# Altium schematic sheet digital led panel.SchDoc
size A4; SheetNumber: 1; SheetTotal: 2; SPICEModelCacheRHZGLBES: <root> / <DocumentId>RHZGLBES</DocumentId> / </root>
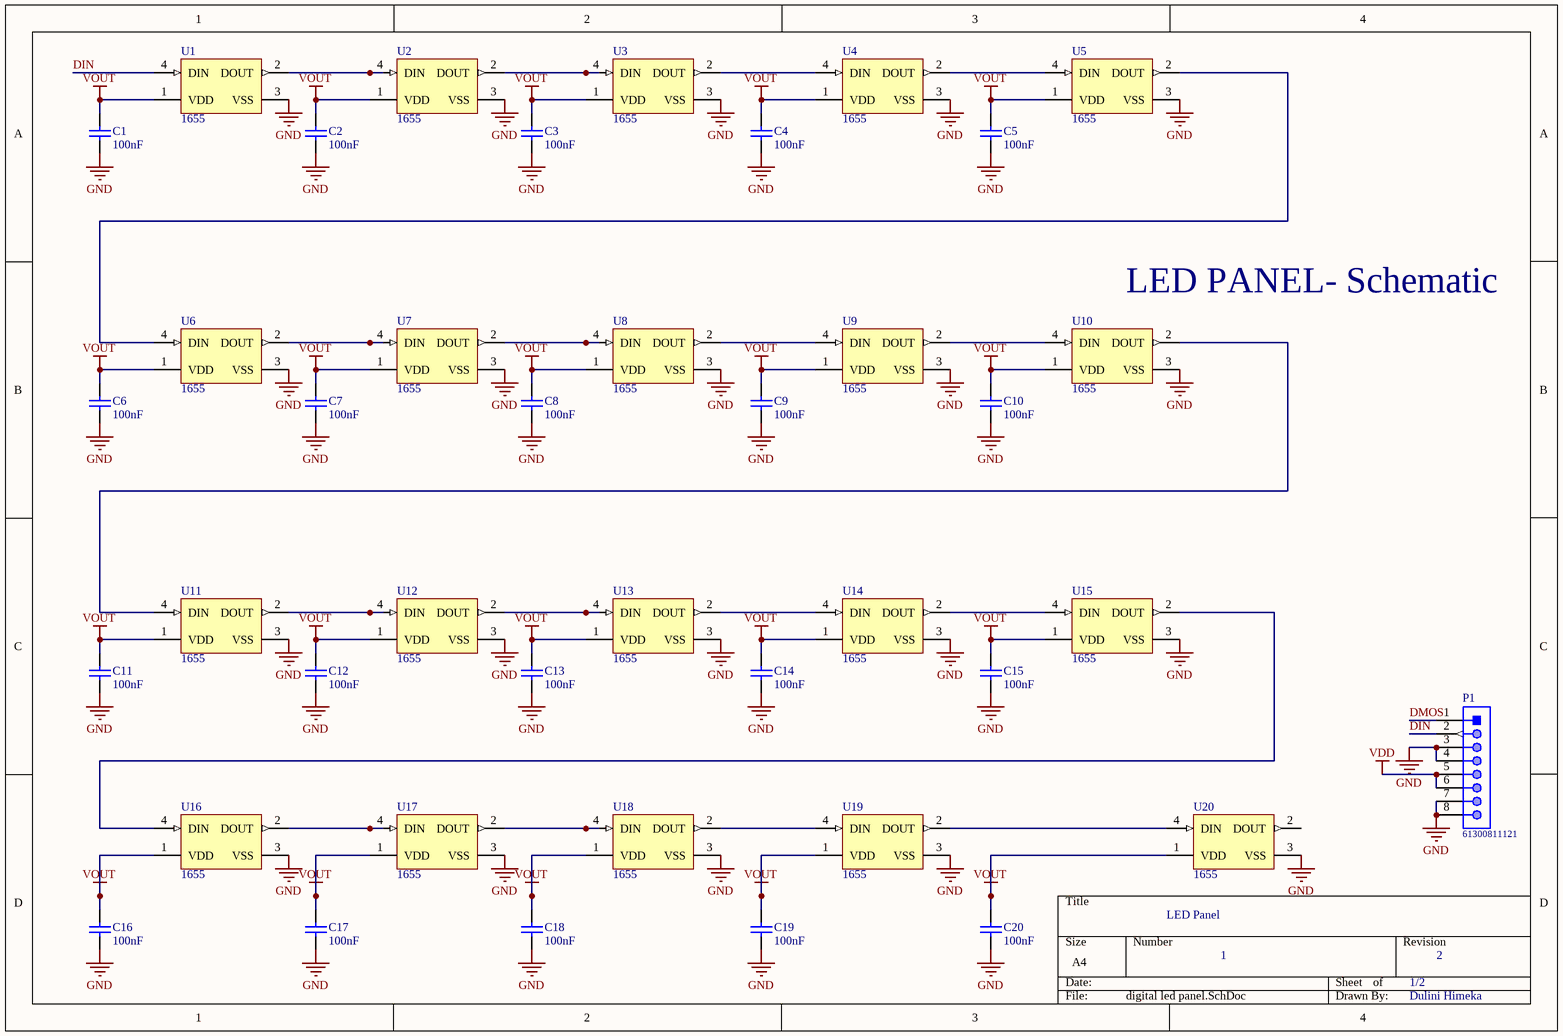
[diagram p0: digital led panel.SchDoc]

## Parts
C1  100nF  [KEMT-1206-2_M]
C2  100nF  [KEMT-1206-2_M]
C3  100nF  [KEMT-1206-2_M]
C4  100nF  [KEMT-1206-2_M]
C5  100nF  [KEMT-1206-2_M]
C6  100nF  [KEMT-1206-2_M]
C7  100nF  [KEMT-1206-2_M]
C8  100nF  [KEMT-1206-2_M]
C9  100nF  [KEMT-1206-2_M]
C10  100nF  [KEMT-1206-2_M]
C11  100nF  [KEMT-1206-2_M]
C12  100nF  [KEMT-1206-2_M]
C13  100nF  [KEMT-1206-2_M]
C14  100nF  [KEMT-1206-2_M]
C15  100nF  [KEMT-1206-2_M]
C16  100nF  [KEMT-1206-2_M]
C17  100nF  [KEMT-1206-2_M]
C18  100nF  [KEMT-1206-2_M]
C19  100nF  [KEMT-1206-2_M]
C20  100nF  [KEMT-1206-2_M]
P1  61300811121  [61300811121]
U1  1655  [ADA-RGB-1655_V]
U2  1655  [ADA-RGB-1655_V]
U3  1655  [ADA-RGB-1655_V]
U4  1655  [ADA-RGB-1655_V]
U5  1655  [ADA-RGB-1655_V]
U6  1655  [ADA-RGB-1655_V]
U7  1655  [ADA-RGB-1655_V]
U8  1655  [ADA-RGB-1655_V]
U9  1655  [ADA-RGB-1655_V]
U10  1655  [ADA-RGB-1655_V]
U11  1655  [ADA-RGB-1655_V]
U12  1655  [ADA-RGB-1655_V]
U13  1655  [ADA-RGB-1655_V]
U14  1655  [ADA-RGB-1655_V]
U15  1655  [ADA-RGB-1655_V]
U16  1655  [ADA-RGB-1655_V]
U17  1655  [ADA-RGB-1655_V]
U18  1655  [ADA-RGB-1655_V]
U19  1655  [ADA-RGB-1655_V]
U20  1655  [ADA-RGB-1655_V]

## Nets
GND: C1.1 C2.1 C3.1 C4.1 C5.1 C6.1 C7.1 C8.1 C9.1 C10.1 C11.1 C12.1 C13.1 C14.1 C15.1 C16.1 C17.1 C18.1 C19.1 C20.1 P1.3 P1.4 P1.7 P1.8 U1.3(VSS) U2.3(VSS) U3.3(VSS) U4.3(VSS) U5.3(VSS) U6.3(VSS) U7.3(VSS) U8.3(VSS) U9.3(VSS) U10.3(VSS) U11.3(VSS) U12.3(VSS) U13.3(VSS) U14.3(VSS) U15.3(VSS) U16.3(VSS) U17.3(VSS) U18.3(VSS) U19.3(VSS) U20.3(VSS)
VDD: P1.5 P1.6
VOUT: C1.2 C2.2 C3.2 C4.2 C5.2 C6.2 C7.2 C8.2 C9.2 C10.2 C11.2 C12.2 C13.2 C14.2 C15.2 C16.2 C17.2 C18.2 C19.2 C20.2 U1.1(VDD) U2.1(VDD) U3.1(VDD) U4.1(VDD) U5.1(VDD) U6.1(VDD) U7.1(VDD) U8.1(VDD) U9.1(VDD) U10.1(VDD) U11.1(VDD) U12.1(VDD) U13.1(VDD) U14.1(VDD) U15.1(VDD) U16.1(VDD) U17.1(VDD) U18.1(VDD) U19.1(VDD) U20.1(VDD)
DIN: P1.2 U1.4(DIN)
DMOS: P1.1
NetU1_2: U1.2(DOUT) U2.4(DIN)
NetU2_2: U2.2(DOUT) U3.4(DIN)
NetU3_2: U3.2(DOUT) U4.4(DIN)
NetU4_2: U4.2(DOUT) U5.4(DIN)
NetU5_2: U5.2(DOUT) U6.4(DIN)
NetU6_2: U6.2(DOUT) U7.4(DIN)
NetU7_2: U7.2(DOUT) U8.4(DIN)
NetU8_2: U8.2(DOUT) U9.4(DIN)
NetU9_2: U9.2(DOUT) U10.4(DIN)
NetU10_2: U10.2(DOUT) U11.4(DIN)
NetU11_2: U11.2(DOUT) U12.4(DIN)
NetU12_2: U12.2(DOUT) U13.4(DIN)
NetU13_2: U13.2(DOUT) U14.4(DIN)
NetU14_2: U14.2(DOUT) U15.4(DIN)
NetU15_2: U15.2(DOUT) U16.4(DIN)
NetU16_2: U16.2(DOUT) U17.4(DIN)
NetU17_2: U17.2(DOUT) U18.4(DIN)
NetU18_2: U18.2(DOUT) U19.4(DIN)
NetU19_2: U19.2(DOUT) U20.4(DIN)

Not connected (* = marked no-connect by the designer): U20 2(DOUT)

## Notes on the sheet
- (near U10) LED PANEL- Schematic
- LED Panel
- 1
- 1/2
- 2
- Dulini Himeka

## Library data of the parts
C1-C20 = CMP-1037-04202-2: CAP, Ceramic, 0.1 uF, +/- 10%, 50 V, -55 to 125 degC, 1206 (3216 Metric), RoHS, Tape and Reel; Manufacturer: Kemet; Voltage Rating: 50V; Capacitance: 0.1µF; Product Range: KEMET-CSeries; SVHC: ToBeAdvised; Dielectric Characteristic: X7R; Capacitor Case Style: 1206[3216Metric]
P1 = CMP-1502-01076-1: THT Vertical Pin Header WR-PHD, Pitch 2.54 mm, Single Row, 8 pins; Manufacturer: Wurth Elektronik; Rated Current: 3A; Pin Number: 8; Working Voltage: 250VAC; Gender: Male; Contact Resistance: 20mOhm; Pitch: 2.54mm; Withstanding Voltage: 500VAC
U1-U20 = CMP-2000-05026-1: Intelligent Control LED Integrated Light Source, 3.5 to 5.3 V, -25 to 80 degC, 4-Pin SMD, RoHS, Tape and Reel; Manufacturer: Adafruit-Industries-LLC; Number of LEDs: 10; Configuration: Discrete; Utilized LED: WS2812(5050)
